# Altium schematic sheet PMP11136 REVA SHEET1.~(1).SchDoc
size 431 x 279 mm; Date: Not shown in title block; ApprovedBy: Not shown in title block; CheckedBy: Not shown in title block; Author: Not shown in title block; CompanyName: Not shown in title block; Engineer: Not shown in title block; Organization: Not shown in title block; Address1: Not shown in title block; Address2: Not shown in title block; Address3: Not shown in title block; Address4: Not shown in title block; DocumentNumber: 1; Revision: Use project parameter SCH_Rev; SheetNumber: 1; SheetTotal: 3; PageSetup: Record=PageOptions¦CenterHorizontal=True¦CenterVertical=True¦PrintScale=1.00¦XCorrection=1.00¦YCorrection=1.00¦PrintKind=0¦BorderSize=5000000¦LeftOffset=0¦BottomOffset=0¦Orientation=2¦PaperLength=1000¦PaperWidth=1000¦Scale=100¦PaperSource=15¦PrintQuality=600¦MediaType=1¦DitherType=10¦PaperKind=Letter¦PrintScaleMode=1
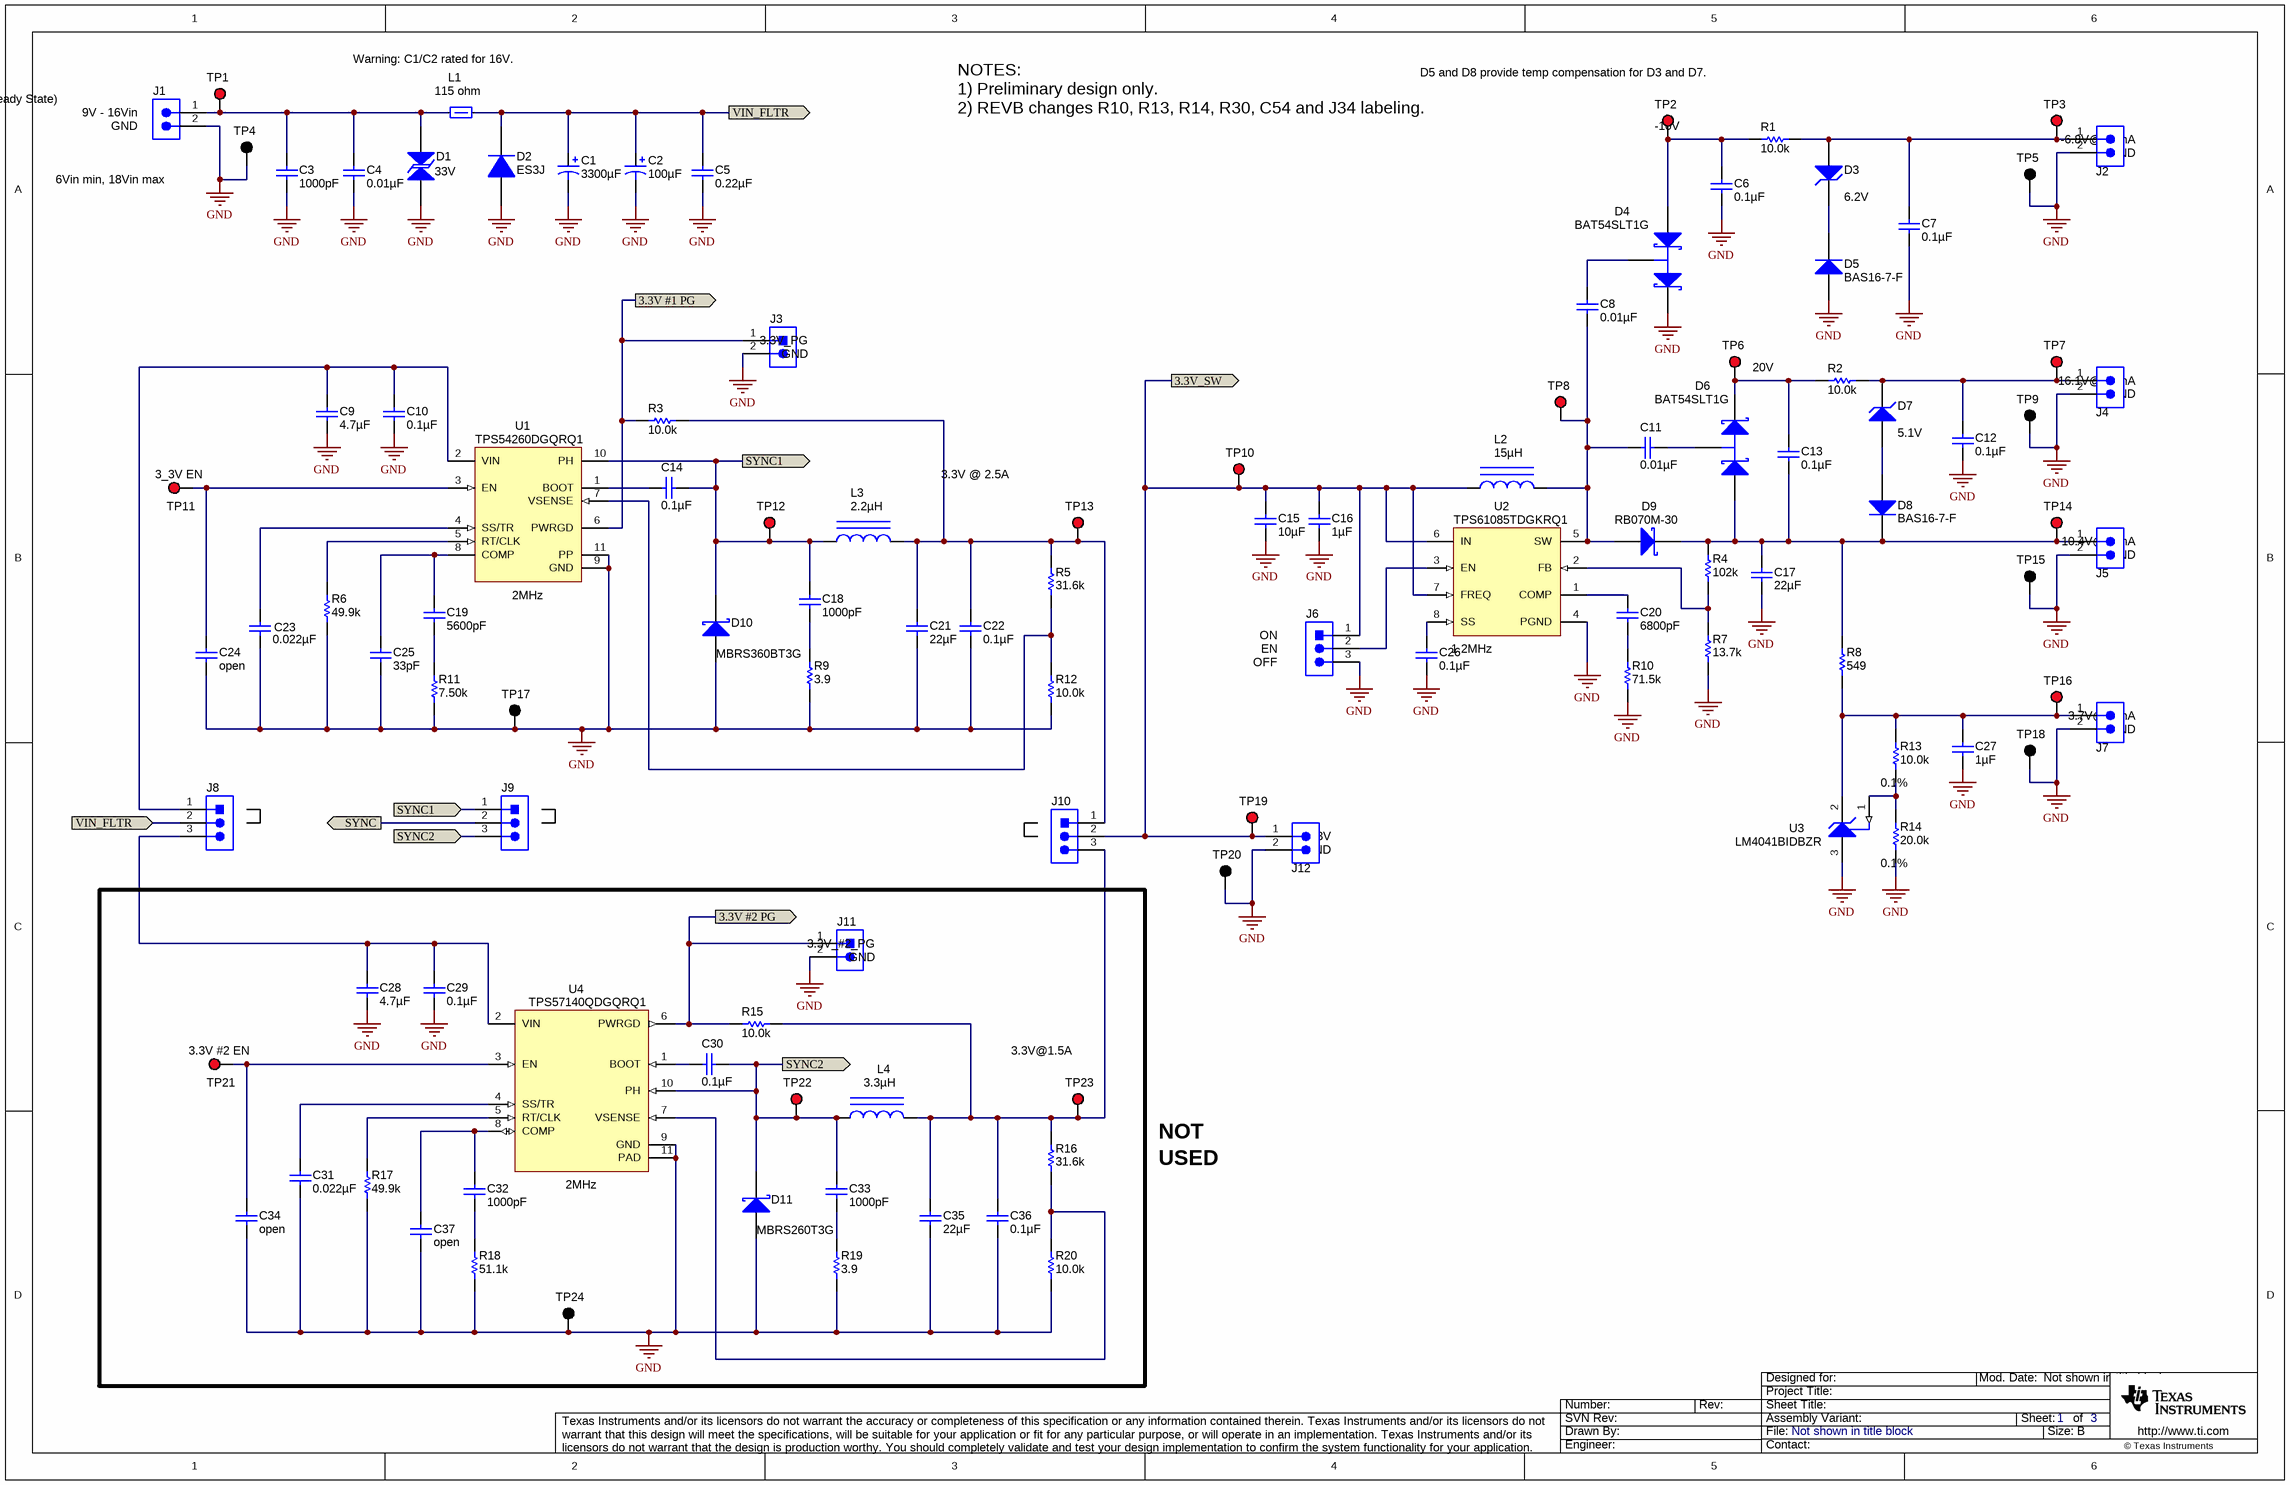
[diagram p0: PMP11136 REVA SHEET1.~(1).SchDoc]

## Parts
C1  ValueDisplayed: 3300µF  [SM_RADIAL_J16]  (hidden comment: EEV-FK1C332M)
C2  ValueDisplayed: 100µF  [SM_RADIAL_D]  (hidden comment: EEE-FK1C101P)
C3  ValueDisplayed: 1000pF  [0603]  (hidden comment: C1608C0G2A102J)
C4  ValueDisplayed: 0.01µF  [0603]  (hidden comment: C1608X7R2A103K)
C5  ValueDisplayed: 0.22µF  [0603]  (hidden comment: C1608X7R1H224K080AB)
C6  ValueDisplayed: 0.1µF  [0603]  (hidden comment: C1608X7R1H104K)
C7  ValueDisplayed: 0.1µF  [0603]  (hidden comment: C1608X7R1H104K)
C8  ValueDisplayed: 0.01µF  [0603]  (hidden comment: C1608X7R1H103K)
C9  ValueDisplayed: 4.7µF  [1210]  (hidden comment: C3225X7R1H475M250AB)
C10  ValueDisplayed: 0.1µF  [0603]  (hidden comment: C1608X7R1H104K)
C11  ValueDisplayed: 0.01µF  [0603]  (hidden comment: C1608X7R1H103K)
C12  ValueDisplayed: 0.1µF  [0603]  (hidden comment: C1608X7R1H104K)
C13  ValueDisplayed: 0.1µF  [0603]  (hidden comment: C1608X7R1H104K)
C14  ValueDisplayed: 0.1µF  [0603]  (hidden comment: C1608X7R1H104K)
C15  ValueDisplayed: 10µF  [0805]  (hidden comment: GRM21BR71A106KE51L)
C16  ValueDisplayed: 1µF  [0603]  (hidden comment: C1608X7R1E105K)
C17  ValueDisplayed: 22µF  [1210]  (hidden comment: C3225X7R1A226M230AC)
C18  ValueDisplayed: 1000pF  [0603]  (hidden comment: C1608C0G2A102J)
C19  ValueDisplayed: 5600pF  [0603]  (hidden comment: C1608C0G1E562J)
C20  ValueDisplayed: 6800pF  [0603]  (hidden comment: C1608C0G1E682J)
C21  ValueDisplayed: 22µF  [1210]  (hidden comment: C3225X7R1A226M230AC)
C22  ValueDisplayed: 0.1µF  [0603]  (hidden comment: C1608X7R1H104K)
C23  ValueDisplayed: 0.022µF  [0603]  (hidden comment: C1608X7R1H223K)
C24  ValueDisplayed: open  [0603]
C25  ValueDisplayed: 33pF  [0603]  (hidden comment: C1608C0G1H330J)
C26  ValueDisplayed: 0.1µF  [0603]  (hidden comment: C1608X7R1H104K)
C27  ValueDisplayed: 1µF  [0603]  (hidden comment: C1608X7R1E105K)
C28  ValueDisplayed: 4.7µF  [1210]  (hidden comment: C3225X7R1H475M250AB)
C29  ValueDisplayed: 0.1µF  [0603]  (hidden comment: C1608X7R1H104K)
C30  ValueDisplayed: 0.1µF  [0603]  (hidden comment: C1608X7R1H104K)
C31  ValueDisplayed: 0.022µF  [0603]  (hidden comment: C1608X7R1H223K)
C32  ValueDisplayed: 1000pF  [0603]  (hidden comment: C1608C0G1H102J)
C33  ValueDisplayed: 1000pF  [0603]  (hidden comment: C1608C0G2A102J)
C34  ValueDisplayed: open  [0603]
C35  ValueDisplayed: 22µF  [1210]  (hidden comment: C3225X7R1A226M230AC)
C36  ValueDisplayed: 0.1µF  [0603]  (hidden comment: C1608X7R1H104K)
C37  ValueDisplayed: open  [0603]
D1  value 33V  [DO-214AB-Bi]  (hidden comment: 1.5SMC33CA-E3/57T)
D2  ES3J  [SMC]
D3  value 6.2V  [SOD-123]  (hidden comment: MMSZ5234B-7-F)
D4  BAT54SLT1G  [SOT-23]
D5  BAS16-7-F  [SOT-23]
D6  BAT54SLT1G  [SOT-23]
D7  value 5.1V  [SOD-123]  (hidden comment: MMSZ5231B-7-F)
D8  BAS16-7-F  [SOT-23]
D9  RB070M-30  [SOD-123]
D10  MBRS360BT3G  [SMB]
D11  MBRS260T3G  [SMB]
J1  ED555/2DS  [TERM_BLK_ED555-2DS]  (value not drawn)
J2  ED555/2DS  [TERM_BLK_ED555-2DS]  (value not drawn)
J3  PEC02SAAN  [CONN_PEC02SAAN]  (value not drawn)
J4  ED555/2DS  [TERM_BLK_ED555-2DS]  (value not drawn)
J5  ED555/2DS  [TERM_BLK_ED555-2DS]  (value not drawn)
J6  PEC03SAAN  [CONN_PEC03SAAN]  (value not drawn)
J7  ED555/2DS  [TERM_BLK_ED555-2DS]  (value not drawn)
J8  PEC03SAAN  [CONN_PEC03SAAN]  (value not drawn)
J9  PEC03SAAN  [CONN_PEC03SAAN]  (value not drawn)
J10  PEC03SAAN  [CONN_PEC03SAAN]  (value not drawn)
J11  PEC02SAAN  [CONN_PEC02SAAN]  (value not drawn)
J12  ED555/2DS  [TERM_BLK_ED555-2DS]  (value not drawn)
L1  value 115 ohm  [28F0181]  (hidden comment: 28F0181-1SR-10)
L2  ValueDisplayed: 15µH  [IND_VLF403215]  (hidden comment: VLF403215MT- 150M)
L3  ValueDisplayed: 2.2µH  [SDR7045]  (hidden comment: SLF6045T-2R2N3R3-3PF)
L4  ValueDisplayed: 3.3µH  [SDR7045]  (hidden comment: SLF6045T-3R3N2R8-3PF)
R1  ValueDisplayed: 10.0k  [0603]  (hidden comment: CRCW060310K0FKEA)
R2  ValueDisplayed: 10.0k  [0603]  (hidden comment: CRCW060310K0FKEA)
R3  ValueDisplayed: 10.0k  [0603]  (hidden comment: CRCW060310K0FKEA)
R4  ValueDisplayed: 102k  [0603]  (hidden comment: CRCW0603102KFKEA)
R5  ValueDisplayed: 31.6k  [0603]  (hidden comment: CRCW060331K6FKEA)
R6  ValueDisplayed: 49.9k  [0603]  (hidden comment: CRCW060349K9FKEA)
R7  ValueDisplayed: 13.7k  [0603]  (hidden comment: CRCW060313K7FKEA)
R8  value 549  [0805_HV]  (hidden comment: CRCW0805549RFKEA)
R9  value 3.9  [2010]  (hidden comment: CRCW20103R90JNEF)
R10  ValueDisplayed: 71.5k  [0603]  (hidden comment: CRCW060371K5FKEA)
R11  ValueDisplayed: 7.50k  [0603]  (hidden comment: CRCW06037K50FKEA)
R12  ValueDisplayed: 10.0k  [0603]  (hidden comment: CRCW060310K0FKEA)
R13  ValueDisplayed: 10.0k  [0603]  (hidden comment: CRCW060310K0FKEA)
R14  ValueDisplayed: 20.0k  [0603]  (hidden comment: CRCW0603210K0FKEA)
R15  ValueDisplayed: 10.0k  [0603]  (hidden comment: CRCW060310K0FKEA)
R16  ValueDisplayed: 31.6k  [0603]  (hidden comment: CRCW060331K6FKEA)
R17  ValueDisplayed: 49.9k  [0603]  (hidden comment: CRCW060349K9FKEA)
R18  ValueDisplayed: 51.1k  [0603]  (hidden comment: CRCW060351K1FKEA)
R19  value 3.9  [2010]  (hidden comment: CRCW20103R90JNEF)
R20  ValueDisplayed: 10.0k  [0603]  (hidden comment: CRCW060310K0FKEA)
TP1  5000  [Keystone5000]  (value not drawn)
TP2  5000  [Keystone5000]  (value not drawn)
TP3  5000  [Keystone5000]  (value not drawn)
TP4  5001  [Keystone5001]  (value not drawn)
TP5  5001  [Keystone5001]  (value not drawn)
TP6  5000  [Keystone5000]  (value not drawn)
TP7  5000  [Keystone5000]  (value not drawn)
TP8  5000  [Keystone5000]  (value not drawn)
TP9  5001  [Keystone5001]  (value not drawn)
TP10  5000  [Keystone5000]  (value not drawn)
TP11  5000  [Keystone5000]  (value not drawn)
TP12  5000  [Keystone5000]  (value not drawn)
TP13  5000  [Keystone5000]  (value not drawn)
TP14  5000  [Keystone5000]  (value not drawn)
TP15  5001  [Keystone5001]  (value not drawn)
TP16  5000  [Keystone5000]  (value not drawn)
TP17  5001  [Keystone5001]  (value not drawn)
TP18  5001  [Keystone5001]  (value not drawn)
TP19  5000  [Keystone5000]  (value not drawn)
TP20  5001  [Keystone5001]  (value not drawn)
TP21  5000  [Keystone5000]  (value not drawn)
TP22  5000  [Keystone5000]  (value not drawn)
TP23  5000  [Keystone5000]  (value not drawn)
TP24  5001  [Keystone5001]  (value not drawn)
U1  TPS54260DGQRQ1  [DGQ0010D_N]
U2  TPS61085TDGKRQ1  [DGK0008A_N]
U3  LM4041BIDBZR  [DBZ0003A_N]
U4  TPS57140QDGQRQ1  [DGQ0010D_N]

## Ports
3.3V #1 PG, 3.3V #2 PG, 3.3V_SW, SYNC, SYNC1, SYNC2, VIN_FLTR

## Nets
GND: C1.2(-) C2.2(-) C3.2 C4.2 C5.2 C6.2 C7.2 C9.1 C10.2 C12.2 C15.2 C16.2 C17.2 C21.2 C22.2 C23.2 C24.2 C25.2 C26.2 C27.2 C28.1 C29.2 C31.2 C34.2 C35.2 C36.2 C37.2 D1.1 D2.2(A) D4.2(K) D5.1(A) D10.2(A) D11.2(A) J1.2 J2.2 J3.2 J4.2 J5.2 J6.3 J7.2 J11.2 J12.2 R6.1 R7.1 R9.1 R10.1 R11.1 R12.1 R14.1 R17.1 R18.1 R19.1 R20.1 TP4.1 TP5.1 TP9.1 TP15.1 TP17.1 TP18.1 TP20.1 TP24.1 U1.9(GND) U1.11(PP) U2.4(PGND) U3.3(ANODE) U4.9(GND) U4.11(PAD)
3.3V #1 PG: J3.1 R3.2 U1.6(PWRGD) ; port 3.3V #1 PG
3.3V #2 PG: J11.1 R15.2 U4.6(PWRGD) ; port 3.3V #2 PG
3.3V_SW: C15.1 C16.1 J6.1 J10.2 J12.1 L2.1 TP10.1 TP19.1 U2.6(IN) U2.7(FREQ) ; port 3.3V_SW
SYNC: J9.2 ; port SYNC
SYNC1: C14.2 C18.1 D10.1(K) J9.1 L3.1 TP12.1 U1.10(PH) ; port SYNC1
SYNC2: C30.2 C33.1 D11.1(K) J9.3 L4.1 TP22.1 U4.10(PH) ; port SYNC2
VIN_FLTR: C1.1(+) C2.1(+) C5.1 D2.1(K) J8.2 L1.2 ; port VIN_FLTR
NetC3_1: C3.1 C4.1 D1.2 J1.1 L1.1 TP1.1
NetC6_1: C6.1 D4.1(A) R1.2 TP2.1
NetC7_1: C7.1 D3.2(A) J2.1 R1.1 TP3.1
NetC8_1: C8.1 C11.1 D9.2(A) L2.2 TP8.1 U2.5(SW)
NetC8_2: C8.2 D4.3(C)
NetC9_2: C9.2 C10.1 J8.1 U1.2(VIN)
NetC11_2: C11.2 D6.3(C)
NetC12_1: C12.1 D7.1(K) J4.1 R2.1 TP7.1
NetC13_1: C13.1 D6.2(K) R2.2 TP6.1
NetC13_2: C13.2 C17.1 D6.1(A) D8.3(K) D9.1(K) J5.1 R4.2 R8.2 TP14.1
NetC14_1: C14.1 U1.1(BOOT)
NetC18_2: C18.2 R9.2
NetC19_1: C19.1 C25.1 U1.8(COMP)
NetC19_2: C19.2 R11.2
NetC20_1: C20.1 U2.1(COMP)
NetC20_2: C20.2 R10.2
NetC21_1: C21.1 C22.1 J10.1 L3.2 R3.1 R5.2 TP13.1
NetC23_1: C23.1 U1.4(SS/TR)
NetC24_1: C24.1 TP11.1 U1.3(EN)
NetC26_1: C26.1 U2.8(SS)
NetC27_1: C27.1 J7.1 R8.1 R13.2 TP16.1 U3.2(CATHODE)
NetC28_2: C28.2 C29.1 J8.3 U4.2(VIN)
NetC30_1: C30.1 U4.1(BOOT)
NetC31_1: C31.1 U4.4(SS/TR)
NetC32_1: C32.1 C37.1 U4.8(COMP)
NetC32_2: C32.2 R18.2
NetC33_2: C33.2 R19.2
NetC34_1: C34.1 TP21.1 U4.3(EN)
NetC35_1: C35.1 C36.1 J10.3 L4.2 R15.1 R16.2 TP23.1
NetD3_1: D3.1(K) D5.3(K)
NetD7_2: D7.2(A) D8.1(A)
NetJ6_2: J6.2 U2.3(EN)
NetR4_1: R4.1 R7.2 U2.2(FB)
NetR5_1: R5.1 R12.2 U1.7(VSENSE)
NetR6_2: R6.2 U1.5(RT/CLK)
NetR13_1: R13.1 R14.2 U3.1(FB)
NetR16_1: R16.1 R20.2 U4.7(VSENSE)
NetR17_2: R17.2 U4.5(RT/CLK)

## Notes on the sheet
- (near J1) (Steady State)
- Warning: C1/C2 rated for 16V.
- D5 and D8 provide temp compensation for D3 and D7.
- (near J1) 9V - 16Vin
- (near J1) GND
- NOTES:
  1) Preliminary design only.
  2) REVB changes R10, R13, R14, R30, C54 and J34 labeling.
- (near TP2) -10V
- (near J2) -6.8V@0.3mA
- (near J2) GND
- (near J1) 6Vin min, 18Vin max
- (near J3) 3.3V_PG
- (near J3) GND
- 20V
- (near J4) 16.1V@0.3mA
- (near J4) GND
- (near TP11) 3_3V EN
- (near TP13) 3.3V @ 2.5A
- (near J5) 10.4V@30mA
- (near J5) GND
- (near U1) 2MHz
- (near J6) ON
- (near J6) EN
- (near J6) OFF
- (near U2) 1.2MHz
- (near J7) 3.7V@10mA
- (near J7) GND
- (near J12) 3.3V
- (near R13) 0.1%
- (near J12) GND
- (near R14) 0.1%
- (near J11) 3.3V_#2_PG
- (near J11) GND
- (near TP21) 3.3V #2 EN
- (near TP23) 3.3V@1.5A
- NOT
- USED
- (near U4) 2MHz

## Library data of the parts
C1 = EEV-FK1C332M: CAP, AL, 3300 µF, 16 V, +/- 20%, 0.035 ohm, SMD; Manufacturer: Panasonic; Polarized: Y; CompType: Capacitor; Value: 3300uF; U/M: EA; Cap_F: 0.0033; Tolerance_%: 20; VDC_V: 16; Value2: 16V; ESR_ohm: 0.035; IRMS_A: 1.8; TaMin_C: -55; TaMax_C: 105; Cap_Case: J16
C2 = EEE-FK1C101P: CAP, AL, 100 µF, 16 V, +/- 20%, 0.36 ohm, SMD; Manufacturer: Panasonic; Polarized: Y; CompType: Capacitor; Value: 100uF; U/M: EA; Cap_F: 0.0001; Tolerance_%: 20; VDC_V: 16; Value2: 16V; ESR_ohm: 0.36; IRMS_A: 0.24; TaMin_C: -55; TaMax_C: 105; Cap_Case: D
C3 C18 C33 = C1608C0G2A102J: CAP, CERM, 1000 pF, 100 V, +/- 5%, C0G/NP0, 0603; Manufacturer: TDK; Polarized: N; CompType: Capacitor; Value: 1000pF; U/M: EA; Cap_F: 0.000000001; Tolerance_%: 5; ESR_ohm: 0.0589; Value1: 0.0589 ohm; VDC_V: 100; Value2: 100V; TaMin_C: -55; TaMax_C: 125
C4 = C1608X7R2A103K: CAP, CERM, 0.01 µF, 100 V, +/- 10%, X7R, 0603; Manufacturer: TDK; Polarized: N; CompType: Capacitor; Value: 0.01uF; U/M: EA; Cap_F: 0.00000001; Tolerance_%: 10; ESR_ohm: 0.0661; Value1: 0.0661 ohm; VDC_V: 100; Value2: 100V; TaMin_C: -55; TaMax_C: 125
C5 = C1608X7R1H224K080AB: CAP, CERM, 0.22 µF, 50 V, +/- 10%, X7R, 0603; Manufacturer: TDK; Polarized: N; CompType: Capacitor; Value: 0.22uF; U/M: EA; Cap_F: 0.00000022; Tolerance_%: 10; Value1: Unknown; VDC_V: 50; Value2: 50V; TaMin_C: -55; TaMax_C: 125
C6 C7 C10 C12-C14 C22 C26 C29 C30 C36 = C1608X7R1H104K: CAP, CERM, 0.1uF, 50V, +/-10%, X7R, 0603; Manufacturer: TDK; Polarized: N; CompType: Capacitor; U/M: EA; Cap_F: 0.0000001; Tolerance_%: 10; ESR_Ohm: 0.017; Value1: 0.017 ohm; VDC_V: 50; TaMin_C: -55; TaMax_C: 125
C8 C11 = C1608X7R1H103K: CAP, CERM, 0.01 µF, 50 V, +/- 10%, X7R, 0603; Manufacturer: TDK; Polarized: N; CompType: Capacitor; Value: 0.01uF; U/M: EA; Cap_F: 0.00000001; Tolerance_%: 10; ESR_ohm: 0.0539; Value1: 0.0539 ohm; VDC_V: 50; Value2: 50V; TaMin_C: -55; TaMax_C: 125
C9 C28 = C3225X7R1E106M: CAP, CERM, 4.7uF, 50V, +/-20%, X7R, 1210; Manufacturer: TDK; Polarized: N; CompType: Capacitor; U/M: EA; Cap_F: 0.00001; Tolerance_%: 20; ESR_Ohm: 0.0027; Value1: 0.0027 ohm; VDC_V: 50; IRMS_A: 3; TaMin_C: -55; TaMax_C: 125
C15 = GRM21BR71A106KE51L: CAP, CERM, 10uF, 10V, +/-10%, X7R, 0805; Manufacturer: MuRata; Polarized: N; CompType: Capacitor; U/M: EA; Cap_F: 0.00001; Tolerance_%: 10; ESR_Ohm: 0.003; Value1: 0.003 ohm; TaMin_C: -55; TaMax_C: 125
C16 C27 = C1608X7R1C105K: CAP, CERM, 1uF, 25V, +/-10%, X7R, 0603; Manufacturer: TDK; Polarized: N; CompType: Capacitor; U/M: EA; Cap_F: 0.000001; Tolerance_%: 10; ESR_Ohm: 0.0057; Value1: 0.0057 ohm; VDC_V: 25; TaMin_C: -55; TaMax_C: 125
C17 C21 C35 = C3225X7R1C226M: CAP, CERM, 22 µF, 16 V, +/- 20%, X7R, 1210; Manufacturer: TDK; Polarized: N; CompType: Capacitor; Value: 22uF; U/M: EA; Cap_F: 0.000022; Tolerance_%: 20; ESR_ohm: 0.002; Value1: 0.002 ohm; VDC_V: 16; Value2: 16V; IRMS_A: 8.11; TaMin_C: -55; TaMax_C: 125
C19 = C1608C0G1E562J: CAP, CERM, 5600 pF, 25 V, +/- 5%, C0G/NP0, 0603; Manufacturer: TDK; Polarized: N; CompType: Capacitor; Value: 5600pF; U/M: EA; Cap_F: 0.0000000056; Tolerance_%: 5; Value1: Unknown; VDC_V: 25; Value2: 25V; TaMin_C: -55; TaMax_C: 125
C20 = C1608C0G1E682J: CAP, CERM, 6800 pF, 25 V, +/- 5%, C0G/NP0, 0603; Manufacturer: TDK; Polarized: N; CompType: Capacitor; Value: 6800pF; U/M: EA; Cap_F: 0.0000000068; Tolerance_%: 5; Value1: Unknown; VDC_V: 25; Value2: 25V; TaMin_C: -55; TaMax_C: 125
C23 C31 = C1608X7R1H223K: CAP, CERM, 0.022 µF, 50 V, +/- 10%, X7R, 0603; Manufacturer: TDK; Polarized: N; CompType: Capacitor; Value: 0.022uF; U/M: EA; Cap_F: 0.000000022; Tolerance_%: 10; ESR_ohm: 0.0383; Value1: 0.0383 ohm; VDC_V: 50; Value2: 50V; TaMin_C: -55; TaMax_C: 125
C24 C34 C37 = C1608C0G1H102J: CAP, CERM, open, 0603; Polarized: N; CompType: Capacitor; U/M: EA; Cap_F: 0.000000001; Tolerance_%: 5; ESR_ohm: 0.0563; TempCo: C0G/NP0; TaMin_C: -55; TaMax_C: 125
C25 = C1608C0G1H330J: CAP, CERM, 33 pF, 50 V, +/- 5%, C0G/NP0, 0603; Manufacturer: TDK; Polarized: N; CompType: Capacitor; Value: 33pF; U/M: EA; Cap_F: 0.000000000033; Tolerance_%: 5; ESR_ohm: 0.2649; Value1: 0.2649 ohm; VDC_V: 50; Value2: 50V; TaMin_C: -55; TaMax_C: 125
C32 = C1608C0G1H102J: CAP, CERM, 1000 pF, 50 V, +/- 5%, C0G/NP0, 0603; Manufacturer: TDK; Polarized: N; CompType: Capacitor; Value: 1000pF; U/M: EA; Cap_F: 0.000000001; Tolerance_%: 5; ESR_ohm: 0.0563; Value1: 0.0563 ohm; VDC_V: 50; Value2: 50V; TaMin_C: -55; TaMax_C: 125
D1 = 1.5SMC33CA-E3/57T: Diode, TVS, Bi, 33V, 1500W, DO-214AB; Manufacturer: Vishay-Dale; U/M: EA; Power_W: 1500; Vr_V: 28.2; RJA_CperW: 75
D2 = ES3D-E3/57T: Diode, Ultrafast, 600V, 3A, SMC; Manufacturer: Fairchild; U/M: EA; Vf_V: 0.9; Value2: 0.9V; Io_A: 3; Vr_V: 600; TJmax_C: 150
D3 = MMSZ5234B-7-F: Diode, Zener, 6.2V, 500 mW, SOD-123; Manufacturer: Diodes Inc.; SymbolCreator: a0412235; U/M: EA; Power_W: 0.5; Vz_V: 6.2; Value1: 0.5W; RJA_CperW: 350
D4 D6 = BAT54SLT1G: Diode, Schottky, 30V, 0.2A, SOT-23; Manufacturer: ON Semiconductor; U/M: EA; Vf_V: 0.8; Value2: 0.8V; Io_A: 0.2; Vr_V: 30; TJmax_C: 150
D5 D8 = BAS16-7-F: Diode, Ultrafast, 75V, 0.3A, SOT-23; Manufacturer: Diodes Inc.; U/M: EA; Vf_V: 1.125; Value2: 1.125V; Io_A: 0.3; Vr_V: 75
D7 = MMSZ5231B-7-F: Diode, Zener, 5.1V, 500 mW, SOD-123; Manufacturer: Diodes Inc.; SymbolCreator: a0412235; U/M: EA; Power_W: 0.5; Vz_V: 5.1; Value1: 0.5W; RJA_CperW: 350
D9 = B130LAW-7-F: Diode, Schottky, 30V, 1.5A, SOD-123; Manufacturer: Rohm; U/M: EA; Vf_V: 0.38; Value1: 1A; Value2: 0.38V; Io_A: 1.5; Vr_V: 30; TJmax_C: 125
D10 = MBRS260T3G: Diode, Schottky, 60V, 3A, SMB; Manufacturer: ON Semiconductor; U/M: EA; Vf_V: 0.63; Value2: 0.63V; Io_A: 2; Vr_V: 60; TJmax_C: 125; RJC_CperW: 24
D11 = MBRS260T3G: Diode, Schottky, 60V, 2A, SMB; Manufacturer: ON Semiconductor; U/M: EA; Vf_V: 0.63; Value2: 0.63V; Io_A: 2; Vr_V: 60; TJmax_C: 125; RJC_CperW: 24
J1 J2 J4 J5 J7 J12 = ED555/2DS: Terminal Block, 6A, 3.5mm Pitch, 2-Pos, TH; Manufacturer: On-Shore Technology, Inc.; SymbolCreator: a0412235; CompType: Connector; U/M: EA
J3 J11 = PEC02SAAN: Header, 100mil, 2x1, Tin, TH; Manufacturer: Sullins Connector Solutions; SymbolCreator: a0412235; U/M: EA
J6 J8-J10 = PEC03SAAN: Header, 100mil, 3x1, Tin, TH; Manufacturer: Sullins Connector Solutions; SymbolCreator: a0799628; U/M: EA
L1 = 28F0181-1SR-10: Ferrite Bead, 115 ohm @ 100MHz, 10A, SMD, 2-Leads, Body 8.74x4.65mm; Manufacturer: Laird-Signal Integrity Products; Imax_A: 10; DCR_ohm: 0.001; Value1: 0.001 ohm; ZTyp@100MHz_Ohm: 115
L2 = VLF403215MT- 150M: Inductor, Shielded, Ferrite, 15uH, 0.87A, 0.22 ohm, SMD; Manufacturer: TDK; Ind_H: 15.0E-6; Imax_A: 0.87; Irms: 0.87A @ 40C rise; Isat: 1.19A @ 30% inductance drop; DCR_ohm: 0.22
L3 = SDR7045-2R2M: Inductor, SMT, 3.3A, 18 milliohm; Manufacturer: Bourns; Value: 2.2uH; Ind_H: 2.2E-6; Imax_A: 3.3; DCR_ohm: 0.032; Material: Ferrite
L4 = SDR7045-2R2M: Inductor, SMT, 2.8A, 21.5 milliohm; Manufacturer: Bourns; Value: 3.3uH; Ind_H: 3.3E-6; Imax_A: 2.8; Material: Ferrite
R1-R3 R12 R15 R20 = CRCW060310K0FKEA: RES, 10.0 k, 1%, 0.1 W, 0603; Manufacturer: Vishay-Dale; CompType: Resistor; Value: 10.0k; Res_ohm: 10000; Value_Code: 10k0; Tolerance_%: 1; Power_W: 0.1; Value2: 0.1W; VDC_V: 75; TempCo: 100 ppm/C; EIA_Code: E96; U/M: EA
R4 = CRCW0603102KFKEA: RES, 102 k, 1%, 0.1 W, 0603; Manufacturer: Vishay-Dale; CompType: Resistor; Value: 102k; Res_ohm: 102000; Tolerance_%: 1; Power_W: 0.1; Value2: 0.1W; VDC_V: 75; TempCo: 100 ppm/C; EIA_Code: E96; U/M: EA
R5 R16 = CRCW060331K6FKEA: RES, 31.6 k, 1%, 0.1 W, 0603; Manufacturer: Vishay-Dale; CompType: Resistor; Value: 31.6k; Res_ohm: 31600; Value_Code: 31k6; Tolerance_%: 1; Power_W: 0.1; Value2: 0.1W; VDC_V: 75; TempCo: 100 ppm/C; EIA_Code: E96; U/M: EA
R6 R17 = CRCW060349K9FKEA: RES, 49.9 k, 1%, 0.1 W, 0603; Manufacturer: Vishay-Dale; CompType: Resistor; Value: 49.9k; Res_ohm: 49900; Value_Code: 49k9; Tolerance_%: 1; Power_W: 0.1; Value2: 0.1W; VDC_V: 75; TempCo: 100 ppm/C; EIA_Code: E96; U/M: EA
R7 = CRCW060313K7FKEA: RES, 13.7 k, 1%, 0.1 W, 0603; Manufacturer: Vishay-Dale; CompType: Resistor; Value: 13.7k; Res_ohm: 13700; Value_Code: 13k7; Tolerance_%: 1; Power_W: 0.1; Value2: 0.1W; VDC_V: 75; TempCo: 100 ppm/C; EIA_Code: E96; U/M: EA
R8 = CRCW0805549RFKEA: RES, 549 ohm, 1%, 0.125W, 0805; Manufacturer: Vishay-Dale; CompType: Resistor; Value_Code: 549R; Tolerance_%: 1; Power_W: 0.125; VDC_V: 150; TempCo: 100 ppm/C; EIA_Code: E96; U/M: EA
R9 R19 = CRCW20102R70JNEF: RES, 3.9 ohm, 5%, 0.75W, 2010; Manufacturer: Vishay-Dale; CompType: Resistor; Value_Code: 3R90; Tolerance_%: 5; Power_W: 0.75; VDC_V: 400; TempCo: 200 ppm/C; EIA_Code: E24; U/M: EA
R10 = CRCW060371K5FKEA: RES, 71.5 k, 1%, 0.1 W, 0603; Manufacturer: Vishay-Dale; CompType: Resistor; Value: 71.5k; Res_ohm: 71500; Value_Code: 71k5; Tolerance_%: 1; Power_W: 0.1; Value2: 0.1W; VDC_V: 75; TempCo: 100 ppm/C; EIA_Code: E96; U/M: EA
R11 = CRCW06037K50FKEA: RES, 7.50 k, 1%, 0.1 W, 0603; Manufacturer: Vishay-Dale; CompType: Resistor; Value: 7.50k; Res_ohm: 7500; Value_Code: 7k50; Tolerance_%: 1; Power_W: 0.1; Value2: 0.1W; VDC_V: 75; TempCo: 100 ppm/C; EIA_Code: E96; U/M: EA
R13 = CRCW060310K0FKEA: RES, 10.0 k, 0.1%, 0.1 W, 0603; Manufacturer: Vishay-Dale; CompType: Resistor; Value: 10.0k; Res_ohm: 10000; Value_Code: 10k0; Tolerance_%: 1; Power_W: 0.1; Value2: 0.1W; VDC_V: 75; TempCo: 100 ppm/C; EIA_Code: E96; U/M: EA
R14 = CRCW060310K0FKEA: RES, 20.0 k, 0.1%, 0.1 W, 0603; Manufacturer: Vishay-Dale; CompType: Resistor; Value: 10.0k; Res_ohm: 10000; Value_Code: 10k0; Tolerance_%: 1; Power_W: 0.1; Value2: 0.1W; VDC_V: 75; TempCo: 100 ppm/C; EIA_Code: E96; U/M: EA
R18 = CRCW060351K1FKEA: RES, 51.1 k, 1%, 0.1 W, 0603; Manufacturer: Vishay-Dale; CompType: Resistor; Value: 51.1k; Res_ohm: 51100; Value_Code: 51k1; Tolerance_%: 1; Power_W: 0.1; Value2: 0.1W; VDC_V: 75; TempCo: 100 ppm/C; EIA_Code: E96; U/M: EA
TP1-TP3 TP6-TP8 TP10-TP14 TP16 TP19 TP21-TP23 = 5000: Test Point, TH, Miniature, Red; Manufacturer: Keystone; CompType: Test Point Loop; U/M: EA
TP4 TP5 TP9 TP15 TP17 TP18 TP20 TP24 = 5001: Test Point, TH, Miniature, Black; Manufacturer: Keystone; CompType: Test Point Loop; U/M: EA
U1 = TPS54260DGQ: Buck Inverting Buck-Boost Step Down Regulator with 3.5 to 60 V Input and 0.8 to 58 V Output, -40 to 150 degC, 10-Pin MSOP-PowerPAD (DGQ), Green (RoHS & no Sb/Br); Manufacturer: Texas Instruments; Alternate Manufacturer: None; Alternate PartNumber: Equivalent; Duty Cycle(Max)(%): 98; Iout(Max)(A): 2.5; Iq(Typ)(mA): 0.138; Rating: Catalog; Regulated Outputs(#): 1; SubFamily: Step-Down Regulator; Switch Current Limit(Typ)(A): 3.5; Topology: Buck, Inverting Buck-Boost; Vin(Max)(V): 60; Vout(Max)(V): 58; Vout(Min)(V): 0.8
U2 = TPS61085TDGKRQ1: Automotive Catalog 18.5 V, 2 A, 650 KHz / 1.2 MHz Step-Up DC-DC Converter with Forced PWM Mode, 2.3 to 6 V, -40 to 105 degC, 8-pin SOP (DGK8), Green (RoHS & no Sb/Br); Manufacturer: Texas Instruments; Alternate Manufacturer: None; Alternate PartNumber: Equivalent; Iout(Max)(A): 2; Iq(Typ)(mA): 0.07; SubFamily: White LED Driver; Switching Frequency(Max)(kHz): 1500; Topology: Boost; Vin(Max)(V): 6; Vin(Min)(V): 2.3
U3 = LM4041BIDBZR: Adjustable Precision Micropower Shunt Voltage Reference, 0.2% accuracy, 15 ppm / degC, 12 mA, -40 to 85 degC, 3-pin SOT-23 (DBZ), Green (RoHS & no Sb/Br); Manufacturer: Texas Instruments; Alternate Manufacturer: None; Alternate PartNumber: Equivalent; Initial Accuracy @ 25/deg C(%): 0.2; Iout/Iz(Max)(mA): 12; Min Iz for Regulation(uA): 60; Rating: Catalog; Temp Coeff(Max)(ppm/ degree C): 100; Temp Coeff(Typ)(ppm/ degree C): 15; VO Adj(Max)(V): 10; VO Adj(Min)(V): 1.225
U4 = TPS57140QDGQRQ1: 1.5-A 42-V STEP-DOWN SWIFT(TM) DC-DC CONVERTER WITH Eco-mode(TM) CONTROL, DGQ0010D; Alternate Manufacturer: None; Manufacturer: Texas Instruments; SymbolCreator: a0799628; CompType: IC; U/M: EA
